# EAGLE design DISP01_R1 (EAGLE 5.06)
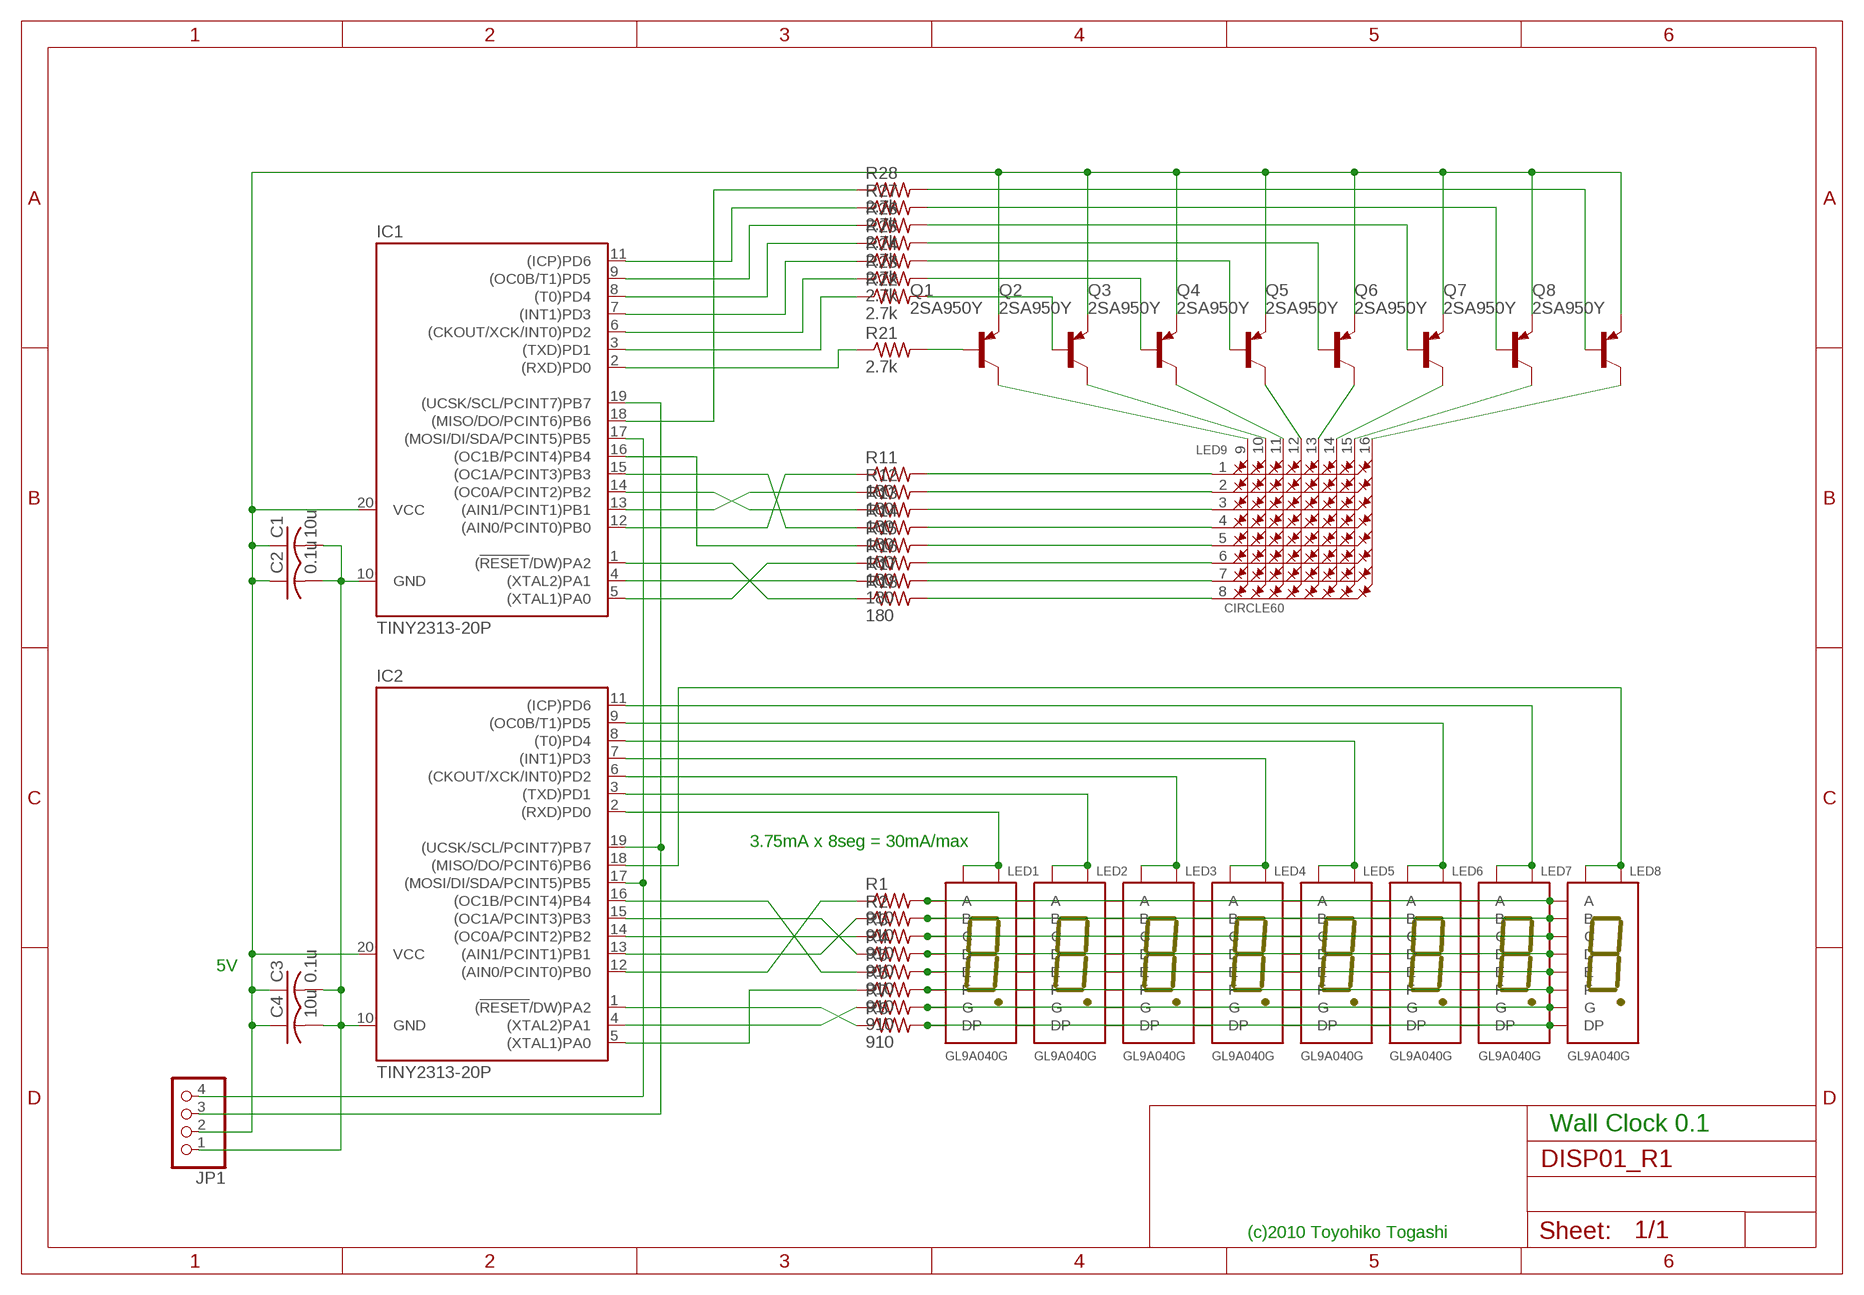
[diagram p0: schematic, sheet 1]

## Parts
C1  10u  C-US025-025X050  [C025-025X050]
C2  0.1u  C-US025-025X050  [C025-025X050]
C3  0.1u  C-US050-025X075  [C050-025X075]
C4  10u  C-US050-025X075  [C050-025X075]
IC1  TINY2313-20P  [DIL20]
IC2  TINY2313-20P  [DIL20]
JP1  PINHD-1X4  [1X04]
LED1  GL9A040G  [GL9A040G]
LED2  GL9A040G  [GL9A040G]
LED3  GL9A040G  [GL9A040G]
LED4  GL9A040G  [GL9A040G]
LED5  GL9A040G  [GL9A040G]
LED6  GL9A040G  [GL9A040G]
LED7  GL9A040G  [GL9A040G]
LED8  GL9A040G  [GL9A040G]
LED9  CIRCLE60  [CIRCLE60]
Q1  2SA950Y  -PNP-TO92-ECB  [TO92-ECB]
Q2  2SA950Y  -PNP-TO92-ECB  [TO92-ECB]
Q3  2SA950Y  -PNP-TO92-ECB  [TO92-ECB]
Q4  2SA950Y  -PNP-TO92-ECB  [TO92-ECB]
Q5  2SA950Y  -PNP-TO92-ECB  [TO92-ECB]
Q6  2SA950Y  -PNP-TO92-ECB  [TO92-ECB]
Q7  2SA950Y  -PNP-TO92-ECB  [TO92-ECB]
Q8  2SA950Y  -PNP-TO92-ECB  [TO92-ECB]
R1  910  R-US_0204/5  [0204/5]
R2  910  R-US_0204/5  [0204/5]
R3  910  R-US_0204/5  [0204/5]
R4  910  R-US_0204/5  [0204/5]
R5  910  R-US_0204/5  [0204/5]
R6  910  R-US_0204/5  [0204/5]
R7  910  R-US_0204/5  [0204/5]
R8  910  R-US_0204/5  [0204/5]
R11  180  R-US_0204/5  [0204/5]
R12  180  R-US_0204/5  [0204/5]
R13  180  R-US_0204/5  [0204/5]
R14  180  R-US_0204/5  [0204/5]
R15  180  R-US_0204/5  [0204/5]
R16  180  R-US_0204/5  [0204/5]
R17  180  R-US_0204/5  [0204/5]
R18  180  R-US_0204/5  [0204/5]
R21  2.7k  R-US_0204/5  [0204/5]
R22  2.7k  R-US_0204/5  [0204/5]
R23  2.7k  R-US_0204/5  [0204/5]
R24  2.7k  R-US_0204/5  [0204/5]
R25  2.7k  R-US_0204/7  [0204/7]
R26  2.7k  R-US_0204/7  [0204/7]
R27  2.7k  R-US_0204/7  [0204/7]
R28  2.7k  R-US_0204/5  [0204/5]

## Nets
N$1: C1.2 C2.2 C3.2 C4.2 IC1.10(GND) IC2.10(GND) JP1.1
N$2: LED1.P$10(A) LED2.P$10(A) LED3.P$10(A) LED4.P$10(A) LED5.P$10(A) LED6.P$10(A) LED7.P$10(A) LED8.P$10(A) R1.2
N$3: C1.1 C2.1 C3.1 C4.1 IC1.20(VCC) IC2.20(VCC) JP1.2 Q1.E Q2.E Q3.E Q4.E Q5.E Q6.E Q7.E Q8.E
N$5: IC1.19((UCSK/SCL/PCINT7)PB7) IC2.19((UCSK/SCL/PCINT7)PB7) JP1.3
N$6: LED1.P$9(B) LED2.P$9(B) LED3.P$9(B) LED4.P$9(B) LED5.P$9(B) LED6.P$9(B) LED7.P$9(B) LED8.P$9(B) R2.2
N$7: LED1.P$8(C) LED2.P$8(C) LED3.P$8(C) LED4.P$8(C) LED5.P$8(C) LED6.P$8(C) LED7.P$8(C) LED8.P$8(C) R3.2
N$8: LED1.P$5(D) LED2.P$5(D) LED3.P$5(D) LED4.P$5(D) LED5.P$5(D) LED6.P$5(D) LED7.P$5(D) LED8.P$5(D) R4.2
N$9: LED1.P$4(E) LED2.P$4(E) LED3.P$4(E) LED4.P$4(E) LED5.P$4(E) LED6.P$4(E) LED7.P$4(E) LED8.P$4(E) R5.2
N$10: LED1.P$2(F) LED2.P$2(F) LED3.P$2(F) LED4.P$2(F) LED5.P$2(F) LED6.P$2(F) LED7.P$2(F) LED8.P$2(F) R6.2
N$11: LED1.P$7(DP) LED2.P$7(DP) LED3.P$7(DP) LED4.P$7(DP) LED5.P$7(DP) LED6.P$7(DP) LED7.P$7(DP) LED8.P$7(DP) R8.2
N$12: LED1.P$3(G) LED2.P$3(G) LED3.P$3(G) LED4.P$3(G) LED5.P$3(G) LED6.P$3(G) LED7.P$3(G) LED8.P$3(G) R7.2
N$14: IC2.5((XTAL1)PA0) R6.1
N$15: IC2.4((XTAL2)PA1) R7.1
N$16: IC2.1((!RESET!/DW)PA2) R8.1
N$17: IC2.12((AIN0/PCINT0)PB0) R1.1
N$18: LED9.1(ROW1) R11.2
N$19: IC2.13((AIN1/PCINT1)PB1) R2.1
N$20: IC2.14((OC0A/PCINT2)PB2) R3.1
N$21: IC2.15((OC1A/PCINT3)PB3) R4.1
N$22: IC2.16((OC1B/PCINT4)PB4) R5.1
N$23: LED9.2(ROW2) R12.2
N$24: LED9.3(ROW3) R13.2
N$25: IC2.2((RXD)PD0) LED1.P$1(CA1) LED1.P$6(CA6)
N$26: LED9.4(ROW4) R14.2
N$27: LED9.5(ROW5) R15.2
N$28: IC2.18((MISO/DO/PCINT6)PB6) LED8.P$1(CA1) LED8.P$6(CA6)
N$29: LED9.6(ROW6) R16.2
N$30: LED9.7(ROW7) R17.2
N$31: LED9.8(ROW8) R18.2
N$32: LED9.9(COL1) Q1.C
N$34: IC1.17((MOSI/DI/SDA/PCINT5)PB5) IC2.17((MOSI/DI/SDA/PCINT5)PB5) JP1.4
N$35: LED9.10(COL2) Q2.C
N$36: Q1.B R21.2
N$37: IC1.5((XTAL1)PA0) R16.1
N$38: IC1.4((XTAL2)PA1) R17.1
N$39: IC1.1((!RESET!/DW)PA2) R18.1
N$40: IC1.12((AIN0/PCINT0)PB0) R11.1
N$41: IC1.13((AIN1/PCINT1)PB1) R12.1
N$42: IC1.14((OC0A/PCINT2)PB2) R13.1
N$43: IC1.15((OC1A/PCINT3)PB3) R14.1
N$44: IC1.16((OC1B/PCINT4)PB4) R15.1
N$45: IC1.2((RXD)PD0) R21.1
N$46: Q2.B R22.2
N$47: Q3.B R23.2
N$48: LED9.11(COL3) Q3.C
N$49: Q4.B R24.2
N$50: Q5.B R25.2
N$51: Q6.B R26.2
N$52: Q7.B R27.2
N$53: IC1.3((TXD)PD1) R22.1
N$54: IC1.6((CKOUT/XCK/INT0)PD2) R23.1
N$55: IC1.7((INT1)PD3) R24.1
N$56: IC1.8((T0)PD4) R25.1
N$57: IC1.9((OC0B/T1)PD5) R26.1
N$58: IC1.11((ICP)PD6) R27.1
N$60: LED9.12(COL4) Q4.C
N$61: Q8.B R28.2
N$62: IC1.18((MISO/DO/PCINT6)PB6) R28.1
N$63: LED9.13(COL5) Q5.C
N$64: LED9.14(COL6) Q6.C
N$65: LED9.15(COL7) Q7.C
N$66: LED9.16(COL8) Q8.C
N$98: IC2.3((TXD)PD1) LED2.P$1(CA1) LED2.P$6(CA6)
N$99: IC2.6((CKOUT/XCK/INT0)PD2) LED3.P$1(CA1) LED3.P$6(CA6)
N$100: IC2.7((INT1)PD3) LED4.P$1(CA1) LED4.P$6(CA6)
N$101: IC2.8((T0)PD4) LED5.P$1(CA1) LED5.P$6(CA6)
N$102: IC2.9((OC0B/T1)PD5) LED6.P$1(CA1) LED6.P$6(CA6)
N$103: IC2.11((ICP)PD6) LED7.P$1(CA1) LED7.P$6(CA6)

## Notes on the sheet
- 3.75mA x 8seg = 30mA/max
- 5V
- Wall Clock 0.1
- (c)2010 Toyohiko Togashi

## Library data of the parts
C1-C4 = rcl:C-US: CAPACITOR, American symbol
IC1 IC2 = TOG:TINY2313: 8-bit AVR Microcontroller with 2K Bytes Flash Source: http://www.atmel.com .. doc2543.pdf
JP1 = pinhead:PINHD-1X4: PIN HEADER
LED1-LED8 = TOG:GL9A040G: 7 Segment LED
LED9 = TOG:CIRCLE60: 60 dot circle line LED 8x8 matrix connection
Q1-Q8 = transistor-neu-to92:*-PNP-: PNP Transistror
R1-R8 R11-R18 R21-R28 = rcl:R-US_: RESISTOR, American symbol

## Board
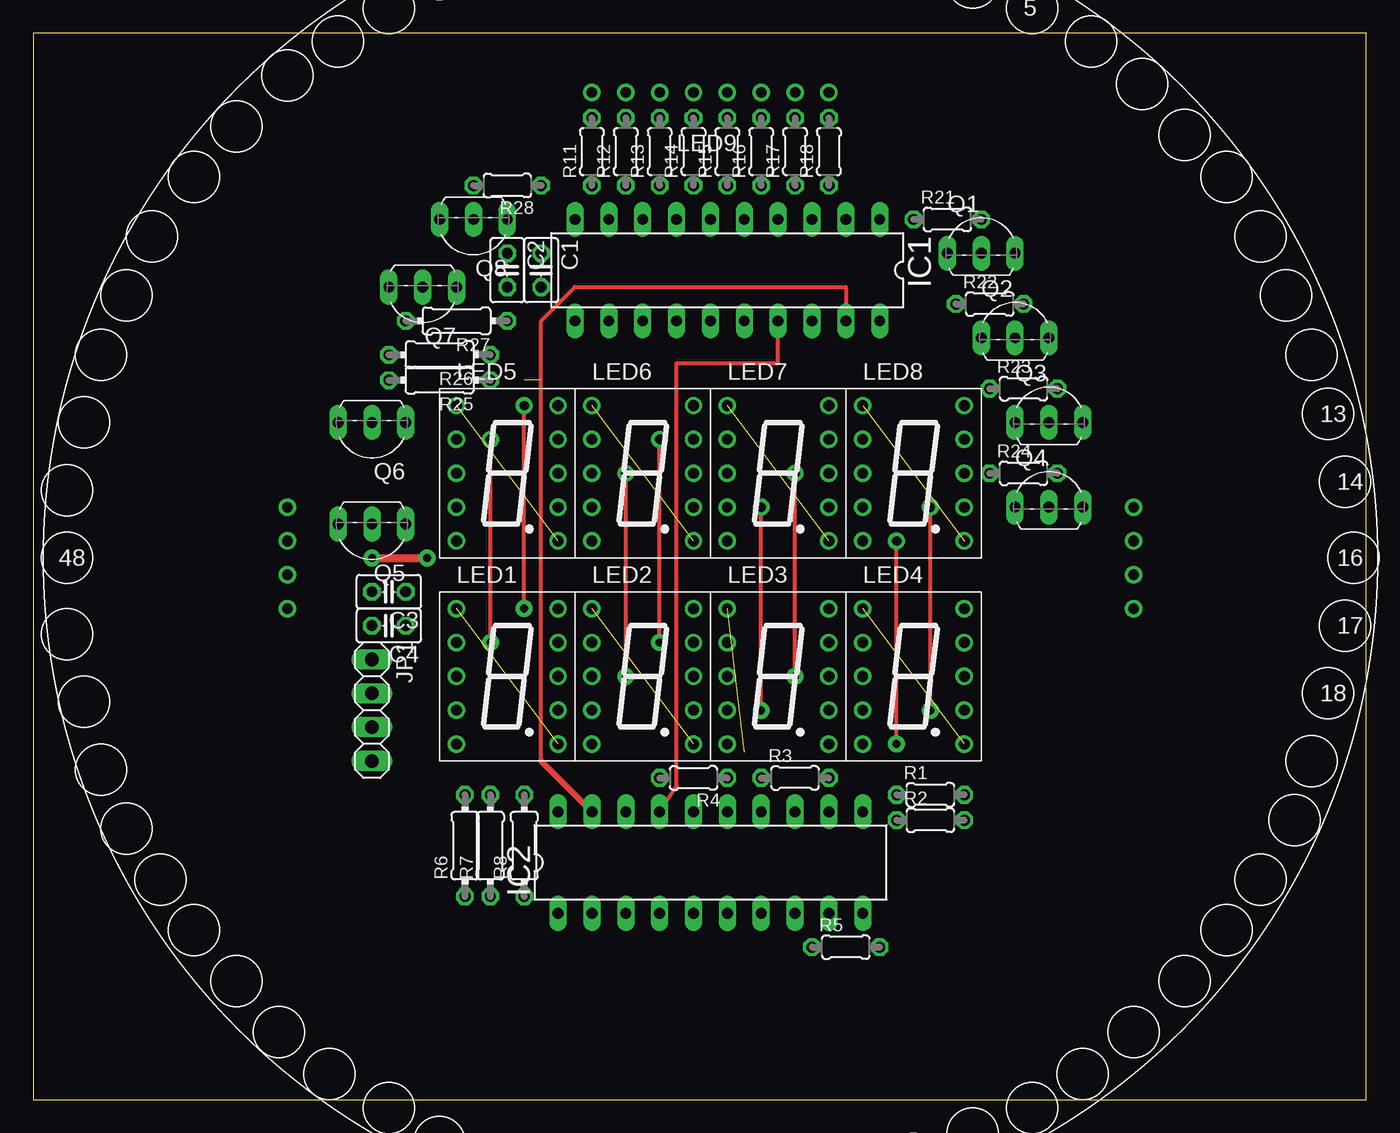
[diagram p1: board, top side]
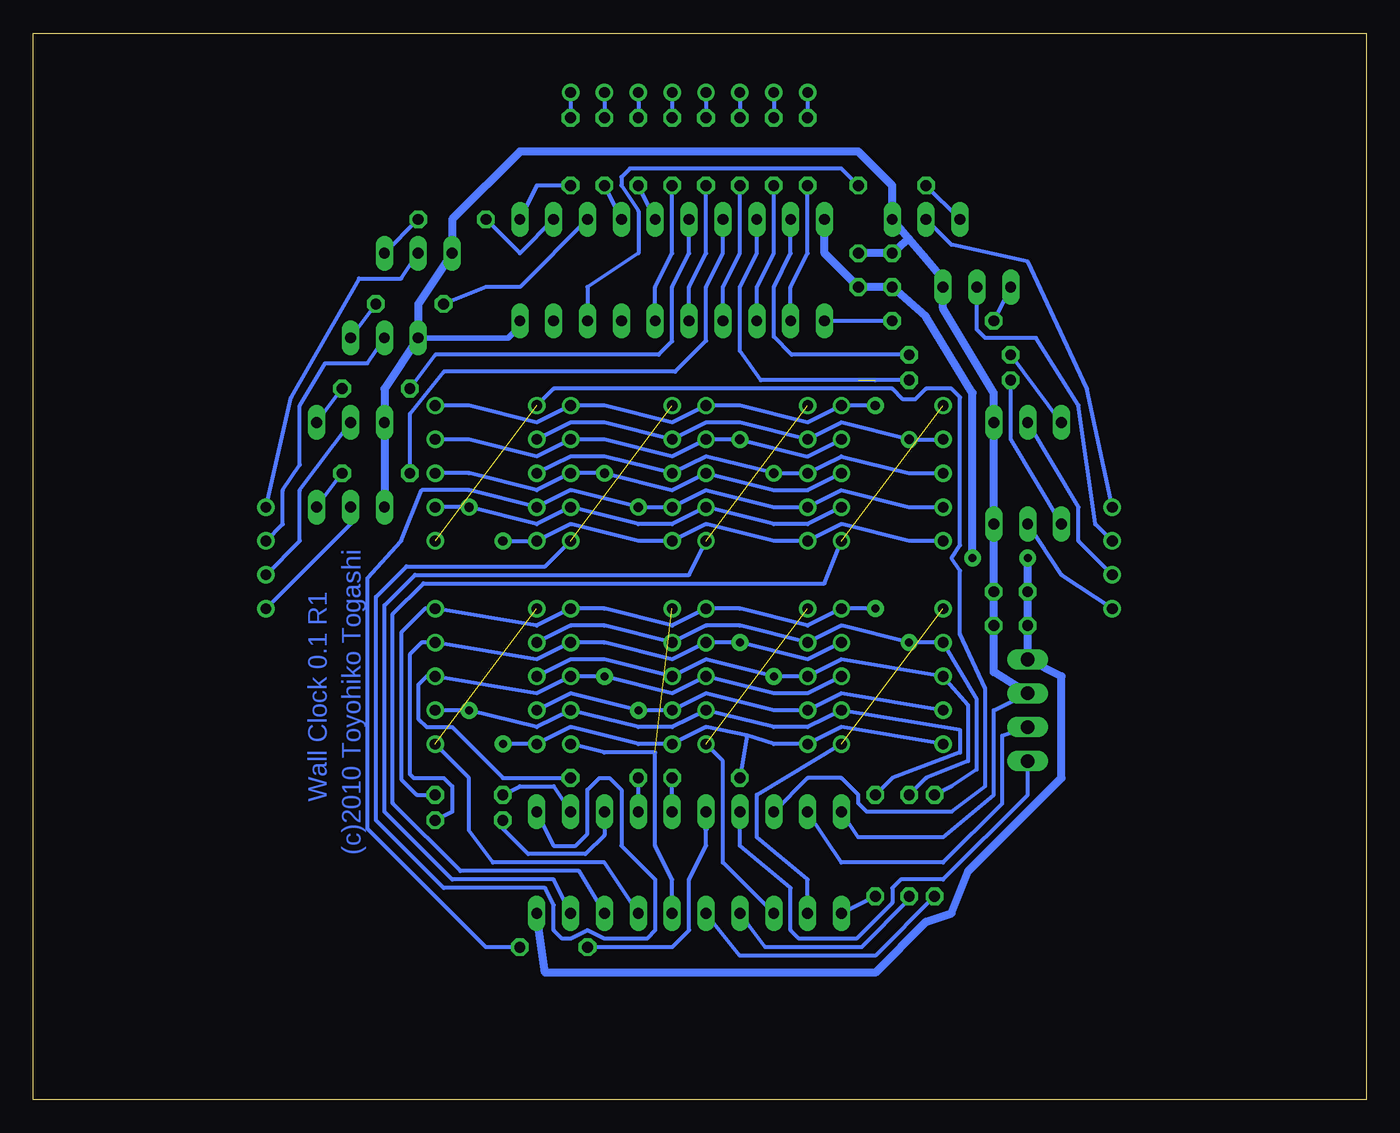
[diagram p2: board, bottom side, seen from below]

Size 100 x 80 mm. Coordinates in mm from the lower left corner, seen from the top.
Outline: 0,0 100,0 100,80 0,80 0,0
Copper layers (1*16): Top 0.035mm / dielectric 1.5mm / Bottom 0.035mm
Design rules "default": minimum track width 10mil, minimum drill 24mil, track to track 8mil, track to pad 8mil, pad to pad 8mil, via to via 8mil, smd to smd 8mil, copper to edge 40mil, drill to drill 8mil, minimum pad ring 10mil, minimum via ring 8mil, stop-mask expansion 4mil, vias tented up to drill 0mil, thermal gap 10mil

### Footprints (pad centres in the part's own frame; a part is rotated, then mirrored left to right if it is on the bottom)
C025-025X050 = drill 0.813 octagon: 1 -1.27,0; 2 1.27,0
DIL20 = drill 0.813 long: 1 -11.43,-3.81; 2 -8.89,-3.81; 3 -6.35,-3.81; 4 -3.81,-3.81; 5 -1.27,-3.81; 6 1.27,-3.81; 7 3.81,-3.81; 8 6.35,-3.81; 9 8.89,-3.81; 10 11.43,-3.81; 11 11.43,3.81; 12 8.89,3.81; 13 6.35,3.81; 14 3.81,3.81; 15 1.27,3.81; 16 -1.27,3.81; 17 -3.81,3.81; 18 -6.35,3.81; 19 -8.89,3.81; 20 -11.43,3.81
1X04 = drill 1.016 long: 1 -3.81,0; 2 -1.27,0; 3 1.27,0; 4 3.81,0
GL9A040G = drill 0.8 round: P$1 -3.81,5.08; P$2 -3.81,2.54; P$3 -3.81,0; P$4 -3.81,-2.54; P$5 -3.81,-5.08; P$6 3.81,-5.08; P$7 3.81,-2.54; P$8 3.81,0; P$9 3.81,2.54; P$10 3.81,5.08
CIRCLE60 = drill 0.8 round: 1 -8.89,34.925; 2 -6.35,34.925; 3 -3.81,34.925; 4 -1.27,34.925; 5 1.27,34.925; 6 3.81,34.925; 7 6.35,34.925; 8 8.89,34.925; 9 31.75,3.81; 10 31.75,1.27; 11 31.75,-1.27; 12 31.75,-3.81; 13 -31.75,-3.81; 14 -31.75,-1.27; 15 -31.75,1.27; 16 -31.75,3.81
TO92-ECB = drill 0.813 long: B 2.54,0; C 0,0; E -2.54,0
0204/5 = drill 0.813 octagon: 1 -2.54,0; 2 2.54,0
0204/7 = drill 0.813 octagon: 1 -3.81,0; 2 3.81,0

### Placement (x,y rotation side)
C1  38.1,62.23 270 top
C2  35.56,62.23 270 top
C3  0.1u  [C025-025X050]  26.67,38.1 180 top
C4  10u  [C025-025X050]  26.67,35.56 180 top
IC1  52.07,62.23 180 top
IC2  50.8,17.78 0 top
JP1  25.4,29.21 270 top
LED1  35.56,31.75 0 top
LED2  45.72,31.75 0 top
LED3  55.88,31.75 0 top
LED4  66.04,31.75 0 top
LED5  35.56,46.99 0 top
LED6  45.72,46.99 0 top
LED7  55.88,46.99 0 top
LED8  66.04,46.99 0 top
LED9  50.8,40.64 0 top
Q1  71.12,63.5 0 top
Q2  73.66,57.15 0 top
Q3  76.2,50.8 0 top
Q4  76.2,44.45 0 top
Q5  25.4,43.18 180 top
Q6  25.4,50.8 180 top
Q7  29.21,60.96 180 top
Q8  33.02,66.04 180 top
R1  67.31,22.86 0 top
R2  67.31,20.95 0 top
R3  57.15,24.13 0 top
R4  49.53,24.13 180 top
R5  60.96,11.43 0 top
R6  910  [0204/7]  32.38,19.05 90 top
R7  910  [0204/7]  34.29,19.05 90 top
R8  910  [0204/7]  36.83,19.05 90 top
R11  41.91,71.12 90 top
R12  44.45,71.12 90 top
R13  46.99,71.12 90 top
R14  49.53,71.12 90 top
R15  52.07,71.12 90 top
R16  54.61,71.12 90 top
R17  57.15,71.12 90 top
R18  59.69,71.12 90 top
R21  68.58,66.04 0 top
R22  71.75,59.69 0 top
R23  74.3,53.34 0 top
R24  74.3,46.99 0 top
R25  30.48,53.98 180 top
R26  30.48,55.88 180 top
R27  31.75,58.42 180 top
R28  35.56,68.58 180 top

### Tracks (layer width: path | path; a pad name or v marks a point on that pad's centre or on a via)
N$1  (via drill 0.6 pad 1.27)
  Top 0.61: v25.4,40.64 v29.53,40.64
  Bottom 0.61: IC2.10 61.59,9.53 36.83,9.53 33.02,13.34 31.11,13.97 29.84,17.14 22.86,24.13 22.86,31.75 JP1.1 C4.2 C3.2 v25.4,40.64 | v29.53,40.64 29.53,53.02 33.02,58.74 C2.2 C1.2 40.64,63.5 IC1.10
N$2  (via drill 0.6 pad 1.27, 0.7 pad 1.27)
  Top 0.305: v36.83,36.83 v36.83,52.07
  Bottom 0.305: v36.83,36.83 LED1.P$10 41.91,35.56 46.99,36.83 LED2.P$10 52.07,35.56 57.15,36.83 LED3.P$10 62.23,35.56 LED4.P$10 70.59,36.83 72.39,35.03 72.39,24.02 71.23,22.86 R1.2 | v36.83,52.07 LED5.P$10 41.91,50.8 46.99,52.07 LED6.P$10 52.07,50.8 57.15,52.07 LED7.P$10 62.23,50.8 67.31,52.07 LED8.P$10
N$3
  Bottom 0.305: 34.3,64.59 34.34,64.64 | JP1.2 27.94,29.21 27.94,22.86 31.75,19.68 38.1,19.68 IC2.20
  Bottom 0.406: Q2.E 64.4,57.15 63.5,58.05 IC1.20
  Bottom 0.61: Q4.E Q3.E 73.66,53.34 Q2.E 71.12,59.69 Q1.E 68.58,66.04 63.5,71.12 38.1,71.12 35.56,68.58 Q8.E 34.34,64.64 | JP1.2 27.94,32.07 C4.1 C3.1 Q5.E Q6.E 27.94,53.02 31.75,59.37 Q7.E 31.75,61.59 33.16,63.27 34.3,64.59 C2.1 C1.1
N$5
  Top 0.305: 38.1,25.4 38.1,58.42 40.64,60.96 60.96,60.96 IC1.19
  Top 0.406: IC2.19 38.1,25.4
  Bottom 0.305: JP1.3 27.3,27.3 27.3,22.23 31.75,17.78 39.37,17.78 IC2.19
N$6  (via drill 0.6 pad 1.27, 0.7 pad 1.27)
  Top 0.305: v46.99,34.29 v46.99,49.53
  Bottom 0.305: LED1.P$9 41.91,33.02 v46.99,34.29 LED2.P$9 52.07,33.02 57.15,34.29 LED3.P$9 62.23,33.02 LED4.P$9 70.86,34.29 71.75,33.39 71.75,24.43 71.45,24.13 69.22,24.13 68.58,23.5 68.58,21.59 R2.2 | LED5.P$9 41.91,48.26 v46.99,49.53 LED6.P$9 52.07,48.26 57.15,49.53 LED7.P$9 62.23,48.26 67.31,49.53 LED8.P$9
N$7  (via drill 0.6 pad 1.27, 0.7 pad 1.27)
  Top 0.305: v57.15,31.75 v57.15,46.99
  Bottom 0.305: LED1.P$8 41.91,30.48 44.45,30.48 LED2.P$8 52.07,30.48 v57.15,31.75 LED3.P$8 62.23,30.48 LED4.P$8 70.48,31.75 71.12,31.11 71.12,28.57 70.48,27.94 68.58,27.94 64.77,24.13 R3.2 | LED5.P$8 41.91,45.72 44.45,45.72 LED6.P$8 52.07,45.72 v57.15,46.99 LED7.P$8 62.23,45.72 67.31,46.99 LED8.P$8
N$8  (via drill 0.6 pad 1.27, 0.7 pad 1.27)
  Top 0.305: v64.77,26.67 v64.77,41.91
  Bottom 0.305: v64.77,26.67 LED4.P$5 59.69,27.94 54.61,26.67 LED3.P$5 49.53,27.94 46.46,27.32 | 46.46,27.32 44.45,26.67 LED2.P$5 39.37,27.94 LED1.P$5 | 46.46,27.32 R4.2 | v64.77,41.91 LED8.P$5 59.69,43.18 54.61,41.91 LED7.P$5 49.53,43.18 44.45,41.91 LED6.P$5 39.37,43.18 34.29,41.91 LED5.P$5
N$9  (via drill 0.6 pad 1.27, 0.7 pad 1.27)
  Top 0.305: v54.61,29.21 v54.61,44.45
  Bottom 0.305: LED1.P$4 39.37,30.48 LED2.P$4 44.45,29.21 49.53,30.48 LED3.P$4 v54.61,29.21 59.69,30.48 LED4.P$4 | R5.2 66.04,11.43 74.93,20.32 74.93,39.11 72.39,41.91 70.86,45.72 67.31,45.72 LED8.P$4 59.69,45.72 v54.61,44.45 LED7.P$4 49.53,45.72 44.45,44.45 LED6.P$4 39.37,45.72 34.29,44.45 LED5.P$4
N$10  (via drill 0.6 pad 1.27, 0.7 pad 1.27)
  Top 0.305: v34.29,34.29 v34.29,49.53
  Bottom 0.305: LED4.P$2 59.69,35.56 57.15,35.56 LED3.P$2 49.53,35.56 46.99,35.56 LED2.P$2 39.37,35.56 v34.29,34.29 LED1.P$2 29.21,30.01 29.21,24.77 31.11,23.5 R6.2 | LED5.P$2 v34.29,49.53 39.37,50.8 LED6.P$2 46.99,50.8 49.53,50.8 LED7.P$2 57.15,50.8 59.69,50.8 LED8.P$2
N$11  (via drill 0.6 pad 1.27, 0.7 pad 1.27)
  Top 0.305: v67.31,29.21 v67.31,44.45
  Bottom 0.305: LED4.P$7 v67.31,29.21 62.23,27.94 LED3.P$7 54.61,27.94 52.07,27.94 LED2.P$7 44.45,27.94 41.91,27.94 LED1.P$7 30.48,27.73 30.48,26.04 35.56,24.13 R8.2 | LED8.P$7 v67.31,44.45 62.23,43.18 LED7.P$7 54.61,43.18 52.07,43.18 LED6.P$7 44.45,43.18 41.91,43.18 LED5.P$7
N$12  (via drill 0.6 pad 1.27, 0.7 pad 1.27)
  Top 0.305: v44.45,31.75 v44.45,46.99
  Bottom 0.305: LED4.P$3 59.69,33.02 57.15,33.02 LED3.P$3 49.53,33.02 v44.45,31.75 LED2.P$3 39.37,33.02 LED1.P$3 29.84,29.58 29.84,25.4 33.02,24.13 R7.2 | LED5.P$3 34.29,46.99 39.37,48.26 LED6.P$3 v44.45,46.99 49.53,48.26 LED7.P$3 57.15,48.26 59.69,48.26 LED8.P$3
N$14
  Bottom 0.305: R6.1 36.83,10.79 46.99,10.79 IC2.5
N$15
  Bottom 0.305: R7.1 34.29,15.02 37.88,11.43 45.09,11.43 IC2.4
N$16
  Bottom 0.305: R8.1 IC2.1
N$17
  Bottom 0.305: R1.1 63.5,23.5 60.96,23.5 IC2.12
N$18
  Bottom 0.305: LED9.1 R11.2
N$19
  Bottom 0.305: R2.1 64.77,20.32 62.87,18.41 58.57,18.41 57.15,19.84 IC2.13
N$20
  Bottom 0.305: IC2.14 R3.1
N$21
  Bottom 0.305: IC2.15 R4.1
N$22
  Bottom 0.305: 49.53,20.32 49.53,19.05 50.8,16.51 50.8,12.7 52.07,11.43 R5.1
  Bottom 0.406: 49.53,20.32 IC2.16
N$23
  Bottom 0.305: LED9.2 R12.2
N$24
  Bottom 0.305: LED9.3 R13.2
N$25  (1 unrouted)
  Bottom 0.305: IC2.2 41.91,16.51 45.72,19.68 45.72,22.86 LED1.P$6
N$26
  Bottom 0.305: LED9.4 R14.2
N$27
  Bottom 0.305: LED9.5 R15.2
N$28  (1 unrouted)
  Bottom 0.305: IC2.18 41.91,24.13 39.37,24.13 38.1,22.86 38.1,22.23 37.47,21.59 31.11,21.59 28.57,23.5 28.57,30.8 30.48,34.92 30.48,39.69 31.11,40.64 30.48,41.59 30.48,52.7 31.11,53.34 33.02,53.34 33.84,52.52 34.74,52.52 35.56,53.34 60.96,53.34 LED8.P$1
N$29
  Bottom 0.305: LED9.6 R16.2
N$30
  Bottom 0.305: LED9.7 R17.2
N$31
  Bottom 0.305: LED9.8 R18.2
N$32
  Bottom 0.305: LED9.9 80.64,52.7 75.56,61.59 72.39,61.59 Q1.C
N$34
  Top 0.305: IC2.17 48.26,23.5 48.26,55.24 55.88,55.24 IC1.17
  Bottom 0.305: JP1.4 25.4,22.86 31.75,16.51 34.92,16.51 35.56,15.88 35.56,14.76 38.25,12.06 42.55,12.06 43.18,12.7 43.18,15.88 46.99,19.05 IC2.17
N$35
  Bottom 0.305: LED9.10 81.28,43.18 81.28,45.72 80.01,47.62 80.01,52.07 78.11,55.24 74.93,55.24 Q2.C
N$36
  Bottom 0.305: Q1.B R21.2
N$37
  Bottom 0.305: IC1.5 R16.1
N$38
  Bottom 0.305: IC1.4 R17.1
N$39
  Bottom 0.305: R18.1 62.23,68.58 IC1.1
N$40
  Bottom 0.305: R11.1 41.91,63.5 43.18,60.96 IC1.12
N$41
  Bottom 0.305: R12.1 44.45,63.5 45.72,60.96 IC1.13
N$42
  Bottom 0.305: R13.1 46.99,63.5 48.26,60.96 IC1.14
N$43
  Bottom 0.305: R14.1 49.53,63.5 50.8,60.96 IC1.15
N$44
  Bottom 0.305: R15.1 52.07,63.5 53.34,60.96 IC1.16
N$45
  Bottom 0.305: IC1.2 63.5,63.5 R21.1
N$46
  Bottom 0.305: Q2.B R22.2
N$47
  Bottom 0.305: Q3.B R23.2
N$48
  Bottom 0.305: LED9.11 80.01,41.91 80.01,45.72 Q3.C
N$49
  Bottom 0.305: Q4.B R24.2
N$50
  Bottom 0.305: Q5.B 26.67,49.53 R25.2
N$51
  Bottom 0.305: Q6.B R26.2
N$52
  Bottom 0.305: R27.2 Q7.B
N$53
  Bottom 0.305: R22.1 66.04,60.96 63.5,60.96 IC1.3
N$54
  Bottom 0.305: R23.1 69.85,55.88 53.09,55.88 52.07,56.9 52.07,60.96 50.8,63.5 IC1.6
N$55
  Bottom 0.305: R24.1 71.75,51.44 69.22,54.61 51.85,54.61 49.53,56.93 49.53,60.96 48.26,63.5 IC1.7
N$56  (1 unrouted)
  Bottom 0.305: R25.1 36.83,53.98 45.42,53.98 46.99,56.18 46.99,60.96 45.72,63.5 IC1.8
N$57
  Bottom 0.305: R26.1 43.1,55.88 44.45,57.23 44.45,60.96 43.18,63.5 IC1.9
N$58
  Bottom 0.305: R27.1 IC1.11
N$60
  Bottom 0.305: Q4.C 76.2,43.18 LED9.12
N$61
  Bottom 0.305: Q8.B R28.2
N$62
  Bottom 0.305: IC1.18 58.42,60.96 54.61,63.5 54.61,66.67 55.88,68.58 55.88,69.22 55.24,69.85 39.37,69.85 R28.1
N$63
  Bottom 0.305: LED9.13 22.86,39.37 Q5.C
N$64
  Bottom 0.305: LED9.14 21.59,41.91 21.59,44.45 Q6.C
N$65
  Bottom 0.305: LED9.15 20.32,43.18 21.59,52.07 24.77,57.15 28.57,57.15 29.21,57.78 Q7.C
N$66
  Bottom 0.305: Q8.C 31.11,64.14 25.4,62.87 20.95,53.34 LED9.16
N$98  (1 unrouted)
  Bottom 0.305: IC2.3 48.26,17.78 48.26,25.4 LED2.P$6
N$99  (1 unrouted)
  Bottom 0.305: IC2.6 52.07,16.51 53.34,19.05 53.34,26.04 57.15,26.04 LED3.P$6
N$100  (1 unrouted)
  Bottom 0.305: IC2.7 57.15,17.78 65.51,17.78 67.31,20.21 67.31,24.13 LED4.P$6
N$101  (1 unrouted)
  Bottom 0.305: IC2.8 59.05,17.14 67.94,17.14 73.03,22.23 73.03,36.45 70.74,38.73 40.64,38.73 LED5.P$6
N$102  (1 unrouted)
  Bottom 0.305: IC2.9 60.96,16.51 68.58,16.51 73.66,21.59 73.66,37.08 71.37,39.37 50.8,39.37 LED6.P$6
N$103  (1 unrouted)
  Bottom 0.305: IC2.11 60.96,19.05 59.32,19.05 58.42,19.95 58.42,23.23 57.52,24.13 56.78,24.13 55.88,23.23 55.88,19.05 53.34,16.51 53.34,12.7 53.98,12.06 57.15,12.06 58.42,12.7 59.69,12.06 60.33,12.06 60.96,12.7 60.96,14.61 61.59,15.88 69.22,15.88 74.3,20.95 74.3,37.72 72,40.01 61.59,40.01 LED7.P$6

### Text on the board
Bottom: (c)2010 Toyohiko Togashi | Wall Clock 0.1 R1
